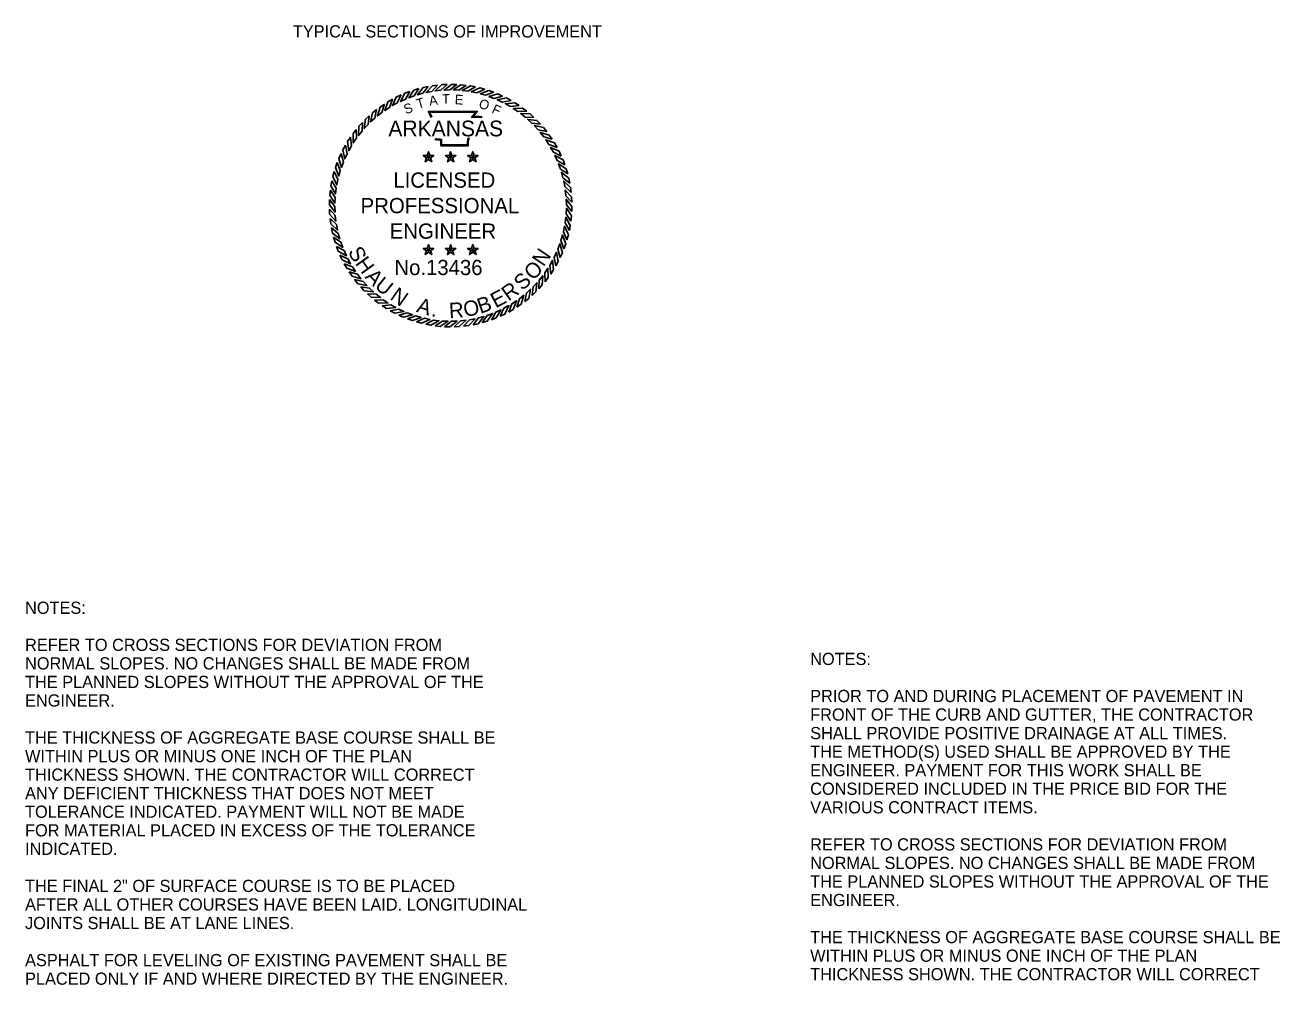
# Model space of a CAD drawing. Extents: x 1398183 to 1398373, y 1967240 to 1968889.
# Drawn here: x 1398308 to 1398369.8, y 1968064.6 to 1968111.8 of the extents above; entities that cross this region are included whole.
import ezdxf

# ---------------------------------------------------------------- set-up
doc = ezdxf.new("R2010")
doc.units = 0
for name, color, linetype in [('1', 7, 'Continuous'), ('19', 7, 'Continuous'), ('G-ANNO-SYMB', 7, 'Continuous')]:
    doc.layers.add(name, color=color, linetype=linetype)

msp = doc.modelspace()

# ---------------------------------------------------------------- linework, layer by layer
at = {"layer": 'G-ANNO-SYMB'}
for points in [[(1398327.422, 1968108.661), (1398327.176, 1968108.589), (1398326.92, 1968108.21), (1398327.181, 1968108.304)], [(1398327.879, 1968108.766), (1398327.628, 1968108.713), (1398327.343, 1968108.355), (1398327.61, 1968108.428)], [(1398328.342, 1968108.834), (1398328.088, 1968108.801), (1398327.776, 1968108.467), (1398328.048, 1968108.519)], [(1398328.81, 1968108.866), (1398328.553, 1968108.853), (1398328.216, 1968108.544), (1398328.492, 1968108.574)], [(1398329.278, 1968108.861), (1398329.021, 1968108.868), (1398328.661, 1968108.587), (1398328.938, 1968108.595)], [(1398329.745, 1968108.819), (1398329.489, 1968108.846), (1398329.108, 1968108.594), (1398329.385, 1968108.581)], [(1398330.206, 1968108.741), (1398329.954, 1968108.788), (1398329.554, 1968108.566), (1398329.829, 1968108.532)], [(1398330.661, 1968108.627), (1398330.413, 1968108.694), (1398329.997, 1968108.504), (1398330.268, 1968108.448)], [(1398326.121, 1968108.138), (1398325.898, 1968108.011), (1398325.738, 1968107.582), (1398325.97, 1968107.735)], [(1398326.54, 1968108.347), (1398326.309, 1968108.237), (1398326.115, 1968107.822), (1398326.358, 1968107.956)], [(1398326.975, 1968108.521), (1398326.735, 1968108.43), (1398326.51, 1968108.032), (1398326.763, 1968108.146)], [(1398331.105, 1968108.477), (1398330.863, 1968108.563), (1398330.433, 1968108.407), (1398330.699, 1968108.33)], [(1398331.535, 1968108.293), (1398331.301, 1968108.398), (1398330.861, 1968108.276), (1398331.12, 1968108.178)], [(1398331.951, 1968108.076), (1398331.725, 1968108.199), (1398331.277, 1968108.112), (1398331.527, 1968107.994)], [(1398325.337, 1968107.627), (1398325.137, 1968107.466), (1398325.046, 1968107.018), (1398325.251, 1968107.204)], [(1398325.719, 1968107.898), (1398325.507, 1968107.753), (1398325.381, 1968107.313), (1398325.6, 1968107.483)], [(1398332.347, 1968107.827), (1398332.132, 1968107.967), (1398331.678, 1968107.915), (1398331.919, 1968107.778)], [(1398332.723, 1968107.548), (1398332.52, 1968107.704), (1398332.063, 1968107.688), (1398332.292, 1968107.533)], [(1398333.076, 1968107.24), (1398332.886, 1968107.412), (1398332.429, 1968107.432), (1398332.646, 1968107.258)], [(1398324.643, 1968106.999), (1398324.471, 1968106.808), (1398324.451, 1968106.351), (1398324.624, 1968106.568)], [(1398324.977, 1968107.326), (1398324.791, 1968107.15), (1398324.735, 1968106.696), (1398324.925, 1968106.898)], [(1398333.404, 1968106.905), (1398333.228, 1968107.091), (1398332.774, 1968107.147), (1398332.976, 1968106.957)], [(1398333.704, 1968106.545), (1398333.543, 1968106.745), (1398333.095, 1968106.836), (1398333.282, 1968106.631)], [(1398324.055, 1968106.27), (1398323.915, 1968106.055), (1398323.967, 1968105.6), (1398324.104, 1968105.841)], [(1398324.335, 1968106.646), (1398324.178, 1968106.442), (1398324.194, 1968105.985), (1398324.35, 1968106.215)], [(1398333.976, 1968106.164), (1398333.831, 1968106.375), (1398333.391, 1968106.501), (1398333.561, 1968106.282)], [(1398323.806, 1968105.873), (1398323.683, 1968105.648), (1398323.771, 1968105.199), (1398323.888, 1968105.45)], [(1398334.216, 1968105.762), (1398334.088, 1968105.984), (1398333.66, 1968106.144), (1398333.812, 1968105.913)], [(1398334.424, 1968105.342), (1398334.314, 1968105.574), (1398333.9, 1968105.767), (1398334.034, 1968105.524)], [(1398323.405, 1968105.027), (1398323.319, 1968104.785), (1398323.475, 1968104.356), (1398323.553, 1968104.622)], [(1398323.589, 1968105.458), (1398323.484, 1968105.224), (1398323.606, 1968104.783), (1398323.704, 1968105.042)], [(1398327.889, 1968105.278), (1398327.828, 1968105.362), (1398327.63, 1968105.362), (1398327.79, 1968105.246)], [(1398327.889, 1968105.278), (1398327.79, 1968105.246), (1398327.729, 1968105.057), (1398327.889, 1968105.174)], [(1398327.889, 1968105.278), (1398327.95, 1968105.362), (1398327.889, 1968105.551), (1398327.828, 1968105.362)], [(1398327.889, 1968105.278), (1398327.988, 1968105.246), (1398328.148, 1968105.362), (1398327.95, 1968105.362)], [(1398327.889, 1968105.278), (1398327.889, 1968105.174), (1398328.049, 1968105.057), (1398327.988, 1968105.246)], [(1398328.98, 1968105.278), (1398328.919, 1968105.362), (1398328.721, 1968105.362), (1398328.881, 1968105.246)], [(1398328.98, 1968105.278), (1398328.881, 1968105.246), (1398328.82, 1968105.057), (1398328.98, 1968105.174)], [(1398328.98, 1968105.278), (1398329.041, 1968105.362), (1398328.98, 1968105.551), (1398328.919, 1968105.362)], [(1398328.98, 1968105.278), (1398329.079, 1968105.246), (1398329.239, 1968105.362), (1398329.041, 1968105.362)], [(1398328.98, 1968105.278), (1398328.98, 1968105.174), (1398329.14, 1968105.057), (1398329.079, 1968105.246)], [(1398330.071, 1968105.278), (1398330.01, 1968105.362), (1398329.812, 1968105.362), (1398329.972, 1968105.246)], [(1398330.071, 1968105.278), (1398329.972, 1968105.246), (1398329.911, 1968105.057), (1398330.071, 1968105.174)], [(1398330.071, 1968105.278), (1398330.132, 1968105.362), (1398330.071, 1968105.551), (1398330.01, 1968105.362)], [(1398330.071, 1968105.278), (1398330.17, 1968105.246), (1398330.33, 1968105.362), (1398330.132, 1968105.362)], [(1398330.071, 1968105.278), (1398330.071, 1968105.174), (1398330.231, 1968105.057), (1398330.17, 1968105.246)], [(1398334.599, 1968104.907), (1398334.508, 1968105.147), (1398334.11, 1968105.372), (1398334.224, 1968105.12)], [(1398334.739, 1968104.46), (1398334.667, 1968104.706), (1398334.288, 1968104.962), (1398334.382, 1968104.701)], [(1398323.256, 1968104.583), (1398323.189, 1968104.335), (1398323.378, 1968103.919), (1398323.434, 1968104.191)], [(1398334.843, 1968104.004), (1398334.791, 1968104.255), (1398334.433, 1968104.539), (1398334.506, 1968104.272)], [(1398323.141, 1968104.129), (1398323.094, 1968103.876), (1398323.316, 1968103.477), (1398323.35, 1968103.752)], [(1398334.912, 1968103.54), (1398334.879, 1968103.795), (1398334.544, 1968104.106), (1398334.596, 1968103.834)], [(1398323.022, 1968103.2), (1398323.014, 1968102.944), (1398323.296, 1968102.583), (1398323.287, 1968102.86)], [(1398323.063, 1968103.667), (1398323.036, 1968103.412), (1398323.288, 1968103.03), (1398323.301, 1968103.307)], [(1398334.944, 1968103.073), (1398334.931, 1968103.329), (1398334.622, 1968103.666), (1398334.652, 1968103.391)], [(1398334.939, 1968102.604), (1398334.946, 1968102.861), (1398334.664, 1968103.221), (1398334.673, 1968102.944)], [(1398323.017, 1968102.732), (1398323.029, 1968102.475), (1398323.338, 1968102.138), (1398323.308, 1968102.414)], [(1398334.897, 1968102.138), (1398334.924, 1968102.393), (1398334.672, 1968102.774), (1398334.659, 1968102.497)], [(1398323.048, 1968102.264), (1398323.081, 1968102.01), (1398323.416, 1968101.698), (1398323.364, 1968101.97)], [(1398334.704, 1968101.222), (1398334.771, 1968101.469), (1398334.582, 1968101.885), (1398334.526, 1968101.614)], [(1398334.819, 1968101.676), (1398334.866, 1968101.928), (1398334.644, 1968102.328), (1398334.61, 1968102.053)], [(1398323.117, 1968101.801), (1398323.169, 1968101.55), (1398323.527, 1968101.265), (1398323.454, 1968101.533)], [(1398323.221, 1968101.344), (1398323.293, 1968101.098), (1398323.672, 1968100.842), (1398323.579, 1968101.103)], [(1398334.555, 1968100.778), (1398334.641, 1968101.019), (1398334.485, 1968101.449), (1398334.407, 1968101.183)], [(1398323.361, 1968100.897), (1398323.452, 1968100.658), (1398323.85, 1968100.432), (1398323.736, 1968100.685)], [(1398327.889, 1968100.71), (1398327.828, 1968100.794), (1398327.63, 1968100.794), (1398327.79, 1968100.677)], [(1398327.889, 1968100.71), (1398327.79, 1968100.677), (1398327.729, 1968100.489), (1398327.889, 1968100.606)], [(1398327.889, 1968100.71), (1398327.95, 1968100.794), (1398327.889, 1968100.982), (1398327.828, 1968100.794)], [(1398327.889, 1968100.71), (1398327.988, 1968100.677), (1398328.148, 1968100.794), (1398327.95, 1968100.794)], [(1398327.889, 1968100.71), (1398327.889, 1968100.606), (1398328.049, 1968100.489), (1398327.988, 1968100.677)], [(1398328.98, 1968100.71), (1398328.919, 1968100.794), (1398328.721, 1968100.794), (1398328.881, 1968100.677)], [(1398328.98, 1968100.71), (1398328.881, 1968100.677), (1398328.82, 1968100.489), (1398328.98, 1968100.606)], [(1398328.98, 1968100.71), (1398329.041, 1968100.794), (1398328.98, 1968100.982), (1398328.919, 1968100.794)], [(1398328.98, 1968100.71), (1398329.079, 1968100.677), (1398329.239, 1968100.794), (1398329.041, 1968100.794)], [(1398328.98, 1968100.71), (1398328.98, 1968100.606), (1398329.14, 1968100.489), (1398329.079, 1968100.677)], [(1398330.071, 1968100.71), (1398330.01, 1968100.794), (1398329.812, 1968100.794), (1398329.972, 1968100.677)], [(1398330.071, 1968100.71), (1398329.972, 1968100.677), (1398329.911, 1968100.489), (1398330.071, 1968100.606)], [(1398330.071, 1968100.71), (1398330.132, 1968100.794), (1398330.071, 1968100.982), (1398330.01, 1968100.794)], [(1398330.071, 1968100.71), (1398330.17, 1968100.677), (1398330.33, 1968100.794), (1398330.132, 1968100.794)], [(1398330.071, 1968100.71), (1398330.071, 1968100.606), (1398330.231, 1968100.489), (1398330.17, 1968100.677)], [(1398334.371, 1968100.347), (1398334.476, 1968100.581), (1398334.354, 1968101.022), (1398334.256, 1968100.762)], [(1398323.536, 1968100.463), (1398323.646, 1968100.231), (1398324.06, 1968100.038), (1398323.926, 1968100.28)], [(1398323.744, 1968100.043), (1398323.872, 1968099.82), (1398324.3, 1968099.66), (1398324.148, 1968099.892)], [(1398333.905, 1968099.535), (1398334.045, 1968099.75), (1398333.993, 1968100.204), (1398333.856, 1968099.963)], [(1398334.154, 1968099.932), (1398334.277, 1968100.157), (1398334.19, 1968100.606), (1398334.072, 1968100.355)], [(1398323.984, 1968099.641), (1398324.129, 1968099.429), (1398324.569, 1968099.303), (1398324.399, 1968099.522)], [(1398333.317, 1968098.806), (1398333.49, 1968098.996), (1398333.509, 1968099.453), (1398333.336, 1968099.237)], [(1398333.625, 1968099.159), (1398333.782, 1968099.362), (1398333.766, 1968099.819), (1398333.61, 1968099.59)], [(1398324.256, 1968099.259), (1398324.417, 1968099.059), (1398324.865, 1968098.968), (1398324.678, 1968099.173)], [(1398324.556, 1968098.9), (1398324.732, 1968098.713), (1398325.186, 1968098.657), (1398324.984, 1968098.847)], [(1398332.623, 1968098.178), (1398332.823, 1968098.339), (1398332.914, 1968098.787), (1398332.709, 1968098.6)], [(1398332.983, 1968098.478), (1398333.169, 1968098.654), (1398333.225, 1968099.108), (1398333.035, 1968098.906)], [(1398324.884, 1968098.565), (1398325.074, 1968098.393), (1398325.531, 1968098.373), (1398325.314, 1968098.546)], [(1398325.237, 1968098.257), (1398325.44, 1968098.1), (1398325.897, 1968098.116), (1398325.668, 1968098.272)], [(1398331.839, 1968097.666), (1398332.062, 1968097.794), (1398332.222, 1968098.222), (1398331.99, 1968098.07)], [(1398332.241, 1968097.907), (1398332.453, 1968098.051), (1398332.579, 1968098.491), (1398332.36, 1968098.321)], [(1398325.613, 1968097.977), (1398325.828, 1968097.837), (1398326.282, 1968097.889), (1398326.041, 1968098.026)], [(1398326.009, 1968097.728), (1398326.235, 1968097.605), (1398326.684, 1968097.693), (1398326.433, 1968097.811)], [(1398326.425, 1968097.511), (1398326.659, 1968097.406), (1398327.099, 1968097.529), (1398326.84, 1968097.627)], [(1398330.538, 1968097.143), (1398330.784, 1968097.216), (1398331.04, 1968097.595), (1398330.779, 1968097.501)], [(1398330.985, 1968097.283), (1398331.225, 1968097.375), (1398331.45, 1968097.773), (1398331.197, 1968097.659)], [(1398331.42, 1968097.458), (1398331.651, 1968097.568), (1398331.845, 1968097.982), (1398331.602, 1968097.849)], [(1398326.855, 1968097.327), (1398327.097, 1968097.241), (1398327.527, 1968097.398), (1398327.261, 1968097.475)], [(1398327.299, 1968097.178), (1398327.547, 1968097.111), (1398327.963, 1968097.301), (1398327.692, 1968097.357)], [(1398327.754, 1968097.064), (1398328.006, 1968097.016), (1398328.406, 1968097.238), (1398328.131, 1968097.273)], [(1398328.216, 1968096.985), (1398328.471, 1968096.958), (1398328.852, 1968097.21), (1398328.575, 1968097.223)], [(1398328.682, 1968096.944), (1398328.939, 1968096.936), (1398329.299, 1968097.218), (1398329.022, 1968097.209)], [(1398329.151, 1968096.939), (1398329.407, 1968096.952), (1398329.744, 1968097.26), (1398329.468, 1968097.23)], [(1398329.618, 1968096.97), (1398329.872, 1968097.003), (1398330.184, 1968097.338), (1398329.912, 1968097.286)], [(1398330.081, 1968097.039), (1398330.332, 1968097.092), (1398330.617, 1968097.449), (1398330.35, 1968097.376)]]:
    msp.add_lwpolyline(points, close=True, dxfattribs=at)
for points in [[(1398328.024, 1968107.232), (1398327.885, 1968107.533), (1398330.292, 1968107.535), (1398330.09, 1968107.282), (1398330.254, 1968107.284), (1398330.391, 1968107.286), (1398330.527, 1968107.271)], [(1398328.059, 1968107.248), (1398327.945, 1968107.495), (1398330.212, 1968107.497), (1398330.011, 1968107.243), (1398330.254, 1968107.246), (1398330.389, 1968107.248), (1398330.523, 1968107.233)], [(1398329.912, 1968106.224), (1398329.871, 1968106.19), (1398329.858, 1968106.14), (1398329.844, 1968106.016), (1398329.844, 1968105.849), (1398328.501, 1968105.849), (1398328.501, 1968106.074), (1398328.501, 1968106.124), (1398328.446, 1968106.14), (1398328.255, 1968106.14), (1398328.221, 1968106.192)], [(1398329.888, 1968106.253), (1398329.838, 1968106.212), (1398329.82, 1968106.148), (1398329.806, 1968106.018), (1398329.806, 1968105.888), (1398328.539, 1968105.888), (1398328.539, 1968106.074), (1398328.539, 1968106.152), (1398328.452, 1968106.179), (1398328.276, 1968106.179), (1398328.253, 1968106.213)]]:
    msp.add_lwpolyline(points, dxfattribs=at)

# ---------------------------------------------------------------- texts
at = {"layer": '1'}
msp.add_text('TYPICAL SECTIONS OF IMPROVEMENT', height=0.6, dxfattribs=at).set_placement((1398321.219, 1968111.175))
at = {"layer": '19'}
for s, p in [('NOTES:', (1398308.047, 1968082.815)), ('REFER TO CROSS SECTIONS FOR DEVIATION FROM', (1398308.047, 1968080.99)), ('NOTES:', (1398346.667, 1968080.297)), ('NORMAL SLOPES. NO CHANGES SHALL BE MADE FROM ', (1398308.047, 1968080.078)), ('THE PLANNED SLOPES WITHOUT THE APPROVAL OF THE', (1398308.047, 1968079.165)), ('PRIOR TO AND DURING PLACEMENT OF PAVEMENT IN', (1398346.667, 1968078.472)), ('ENGINEER.', (1398308.047, 1968078.253)), ('FRONT OF THE CURB AND GUTTER, THE CONTRACTOR', (1398346.667, 1968077.56)), ('SHALL PROVIDE POSITIVE DRAINAGE AT ALL TIMES.', (1398346.667, 1968076.647)), ('THE THICKNESS OF AGGREGATE BASE COURSE SHALL BE', (1398308.047, 1968076.428)), ('WITHIN PLUS OR MINUS ONE INCH OF THE PLAN ', (1398308.047, 1968075.515)), ('THE METHOD(S) USED SHALL BE APPROVED BY THE', (1398346.667, 1968075.735)), ('ENGINEER. PAYMENT FOR THIS WORK SHALL BE', (1398346.667, 1968074.822)), ('THICKNESS SHOWN. THE CONTRACTOR WILL CORRECT', (1398308.047, 1968074.603)), ('ANY DEFICIENT THICKNESS THAT DOES NOT MEET', (1398308.047, 1968073.69)), ('CONSIDERED INCLUDED IN THE PRICE BID FOR THE', (1398346.667, 1968073.91)), ('VARIOUS CONTRACT ITEMS.', (1398346.667, 1968072.997)), ('TOLERANCE INDICATED. PAYMENT WILL NOT BE MADE', (1398308.047, 1968072.778)), ('FOR MATERIAL PLACED IN EXCESS OF THE TOLERANCE', (1398308.047, 1968071.865)), ('REFER TO CROSS SECTIONS FOR DEVIATION FROM', (1398346.667, 1968071.172)), ('INDICATED.', (1398308.047, 1968070.953)), ('NORMAL SLOPES. NO CHANGES SHALL BE MADE FROM ', (1398346.667, 1968070.26)), ('THE PLANNED SLOPES WITHOUT THE APPROVAL OF THE', (1398346.667, 1968069.347)), ('THE FINAL 2" OF SURFACE COURSE IS TO BE PLACED', (1398308.047, 1968069.128)), ('AFTER ALL OTHER COURSES HAVE BEEN LAID. LONGITUDINAL', (1398308.047, 1968068.215)), ('ENGINEER.', (1398346.667, 1968068.435)), ('JOINTS SHALL BE AT LANE LINES.', (1398308.047, 1968067.303)), ('THE THICKNESS OF AGGREGATE BASE COURSE SHALL BE', (1398346.667, 1968066.61)), ('ASPHALT FOR LEVELING OF EXISTING PAVEMENT SHALL BE', (1398308.047, 1968065.478)), ('WITHIN PLUS OR MINUS ONE INCH OF THE PLAN ', (1398346.667, 1968065.697)), ('PLACED ONLY IF AND WHERE DIRECTED BY THE ENGINEER.', (1398308.047, 1968064.565)), ('THICKNESS SHOWN. THE CONTRACTOR WILL CORRECT', (1398346.667, 1968064.785))]:
    msp.add_text(s, height=0.6, dxfattribs=at).set_placement(p)
at = {"layer": 'G-ANNO-SYMB'}
for s, height, rotation, p in [('T', 0.475, 16.90148, (1398327.375, 1968107.661)), ('A', 0.475, 8.67877, (1398327.951, 1968107.812)), ('T', 0.475, 1.47887, (1398328.564, 1968107.906)), ('E', 0.475, 356.67203, (1398329.171, 1968107.892)), ('O', 0.475, 341.2218, (1398330.324, 1968107.729)), ('S', 0.475, 19.77256, (1398326.771, 1968107.39)), ('F', 0.475, 335.36282, (1398330.964, 1968107.479)), ('S', 0.75, 298.16364, (1398323.912, 1968100.642)), ('N', 0.75, 56.10067, (1398333.554, 1968099.859)), ('H', 0.75, 305.61905, (1398324.254, 1968100.055)), ('O', 0.75, 44.77573, (1398333.033, 1968099.184)), ('A', 0.75, 313.44722, (1398324.73, 1968099.37)), ('U', 0.75, 320.90262, (1398325.198, 1968098.881)), ('S', 0.75, 43.48784, (1398332.518, 1968098.686)), ('N', 0.75, 324.93262, (1398325.954, 1968098.322)), ('E', 0.75, 27.83149, (1398331.194, 1968097.844)), ('R', 0.75, 35.65967, (1398331.828, 1968098.176)), ('A', 0.75, 343.09908, (1398327.261, 1968097.679)), ('O', 0.75, 11.42961, (1398329.685, 1968097.414)), ('B', 0.75, 18.88501, (1398330.437, 1968097.573)), ('.', 0.75, 351.30002, (1398327.998, 1968097.46)), ('R', 0.75, 3.22866, (1398328.918, 1968097.366))]:
    msp.add_text(s, height=height, rotation=rotation, dxfattribs=at).set_placement(p)
for s, height, p in [('ARKANSAS', 0.7747, (1398325.918, 1968106.31)), ('LICENSED', 0.75, (1398326.159, 1968103.782)), ('PROFESSIONAL', 0.75, (1398324.551, 1968102.527)), ('ENGINEER', 0.75, (1398325.98, 1968101.273)), ('No.13436', 0.747, (1398326.217, 1968099.485))]:
    msp.add_text(s, height=height, dxfattribs=at).set_placement(p)

doc.saveas('drawing.dxf')
